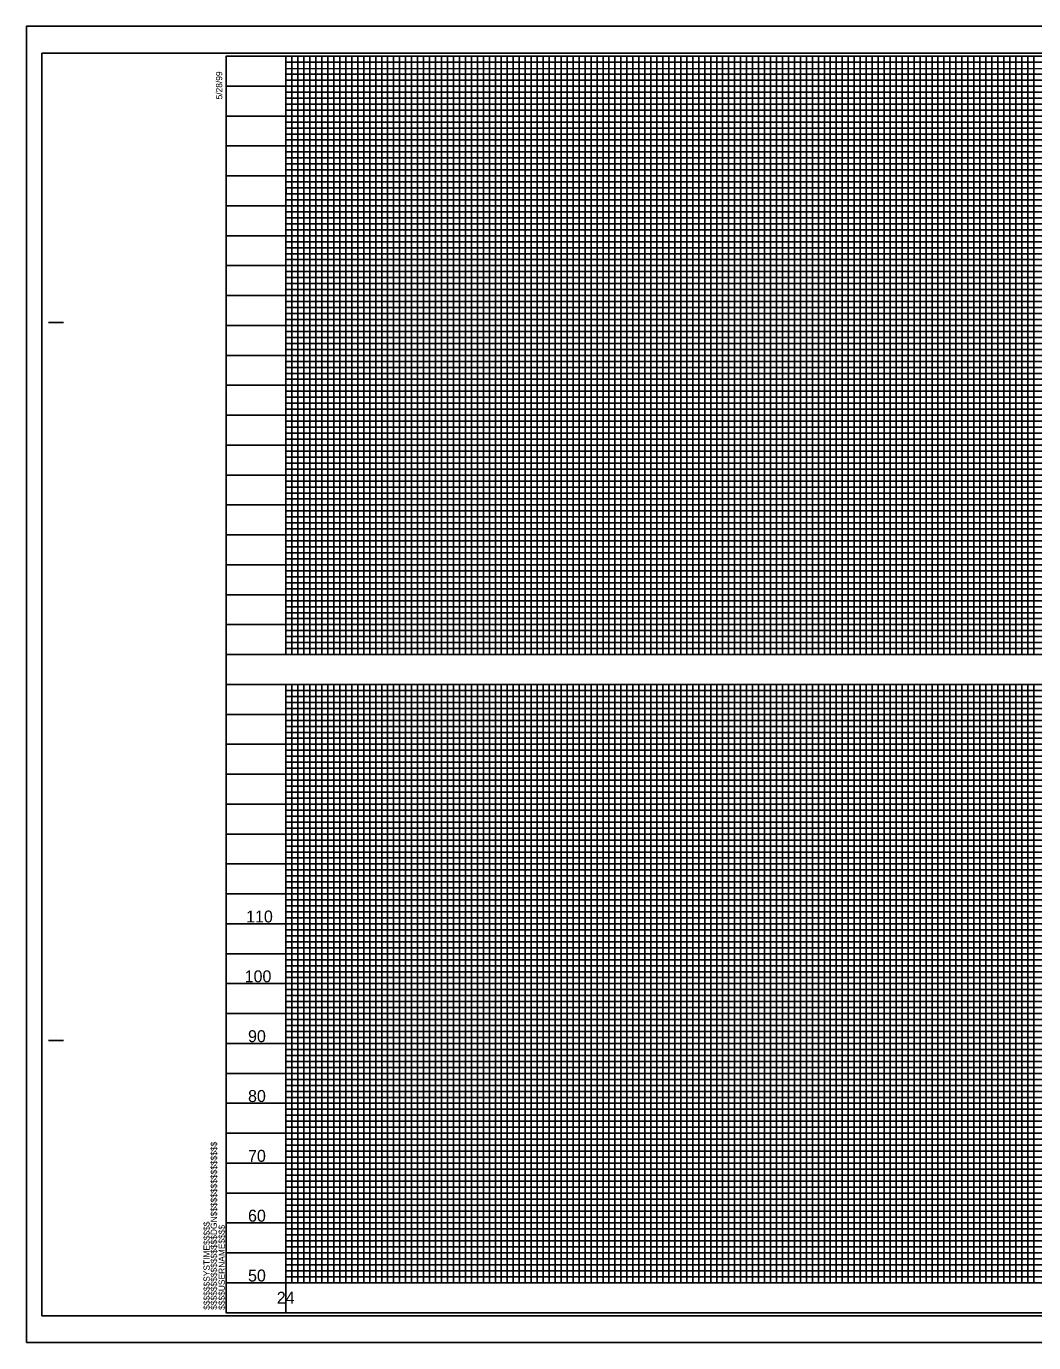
# Model space of a CAD drawing. Extents: x 2367101 to 2368930, y 803279 to 808979.
# Drawn here: x 2367101 to 2367943, y 803279 to 804379 of the extents above; entities that cross this region are included whole.
import ezdxf

# ---------------------------------------------------------------- set-up
doc = ezdxf.new("R2010")
doc.units = 0
for name, color, linetype in [('Old_Level_11', 7, 'Continuous'), ('Old_Level_12', 7, 'Continuous'), ('Old_Level_13', 7, 'Continuous'), ('Old_Level_14', 7, 'Continuous'), ('Old_Level_15', 7, 'Continuous'), ('Old_Level_17', 7, 'Continuous'), ('Old_Level_19', 7, 'Continuous'), ('Old_Level_4', 7, 'Continuous'), ('Old_Level_5', 7, 'Continuous'), ('Old_Level_6', 7, 'Continuous'), ('Old_Level_63', 7, 'Continuous'), ('Old_Level_8', 7, 'Continuous'), ('Old_Level_9', 7, 'Continuous')]:
    doc.layers.add(name, color=color, linetype=linetype)

msp = doc.modelspace()

# ---------------------------------------------------------------- linework, layer by layer
at = {"layer": 'Old_Level_11'}
for p, q in [((2367768, 803829), (2367818, 803829)), ((2367868, 803829), (2367918, 803829)), ((2367268, 803329), (2367268, 803329))]:
    msp.add_line(p, q, dxfattribs=at)
for points in [[(2367318, 804354), (2367318, 803854), (2367368, 803854), (2367368, 804354), (2367418, 804354), (2367418, 803854), (2367468, 803854), (2367468, 804354), (2367518, 804354), (2367518, 803854), (2367568, 803854), (2367568, 804354), (2367618, 804354), (2367618, 803854), (2367668, 803854), (2367668, 804354), (2367718, 804354), (2367718, 803854), (2367768, 803854), (2367768, 804354), (2367818, 804354), (2367818, 803854), (2367868, 803854), (2367868, 804354), (2367918, 804354), (2367918, 803854), (2367968, 803854)], [(2367268, 804304), (2368568, 804304)], [(2368568, 804254), (2367268, 804254), (2367268, 804204), (2368568, 804204)], [(2368768, 804154), (2367268, 804154), (2367268, 804104), (2368768, 804104)], [(2368768, 804054), (2367268, 804054), (2367268, 804004), (2368768, 804004)], [(2368768, 803954), (2367268, 803954), (2367268, 803954), (2367268, 803904), (2368768, 803904)], [(2367318, 803829), (2367318, 803329), (2367368, 803329), (2367368, 803829), (2367418, 803829), (2367418, 803329), (2367468, 803329), (2367468, 803829), (2367518, 803829), (2367518, 803329), (2367568, 803329), (2367568, 803829), (2367618, 803829), (2367618, 803329), (2367668, 803329), (2367668, 803829), (2367718, 803829), (2367718, 803329), (2367768, 803329), (2367768, 803829), (2367818, 803829), (2367818, 803329), (2367868, 803329), (2367868, 803829), (2367918, 803829), (2367918, 803329), (2367968, 803329)], [(2368768, 803779), (2367268, 803779)], [(2368768, 803729), (2367268, 803729), (2367268, 803679), (2368768, 803679)], [(2368768, 803629), (2367268, 803629), (2367268, 803579), (2368768, 803579)], [(2368768, 803529), (2367268, 803529), (2367268, 803479), (2368768, 803479)], [(2368768, 803429), (2367268, 803429), (2367268, 803429), (2367268, 803379), (2368768, 803379)], [(2368768, 803329), (2367268, 803329)]]:
    msp.add_lwpolyline(points, dxfattribs=at)
at = {"layer": 'Old_Level_12'}
msp.add_line((2367268, 804329), (2368567.9, 804329), dxfattribs=at)
for points in [[(2367343, 804354), (2367343, 803854), (2367393, 803854), (2367393, 804354), (2367443, 804354), (2367443, 803854), (2367493, 803854), (2367493, 804354), (2367543, 804354), (2367543, 803854), (2367593, 803854), (2367593, 804354), (2367643, 804354), (2367643, 803854), (2367693, 803854), (2367693, 804354), (2367743, 804354), (2367743, 803854), (2367793, 803854), (2367793, 804354), (2367843, 804354), (2367843, 803854), (2367893, 803854), (2367893, 803854), (2367893, 804354), (2367943, 804354), (2367943, 803854), (2367993, 803854)], [(2368568, 804279), (2367268, 804279), (2367268, 804229), (2368568, 804229)], [(2368768, 804179), (2367268, 804179), (2367268, 804129), (2368593, 804129)], [(2368768, 804079), (2367268, 804079), (2367268, 804029), (2368768, 804029)], [(2368768, 803979), (2367268, 803979), (2367268, 803929), (2368768, 803929)], [(2368768, 803879), (2367268, 803879)], [(2367293, 803829), (2367343, 803829), (2367343, 803329), (2367393, 803329), (2367393, 803829), (2367443, 803829), (2367443, 803329), (2367493, 803329), (2367493, 803829), (2367543, 803829), (2367543, 803329), (2367593, 803329), (2367593, 803829), (2367643, 803829), (2367643, 803329), (2367693, 803329), (2367693, 803829), (2367743, 803829), (2367743, 803329), (2367793, 803329), (2367793, 803829), (2367843, 803829), (2367843, 803329), (2367893, 803329), (2367893, 803329), (2367893, 803829), (2367943, 803829), (2367943, 803329), (2367993, 803329)], [(2367268, 803804), (2368768, 803804)], [(2368768, 803754), (2367268, 803754), (2367268, 803704), (2368768, 803704)], [(2368768, 803654), (2367268, 803654), (2367268, 803604), (2368768, 803604)], [(2368768, 803554), (2367268, 803554), (2367268, 803504), (2368768, 803504)], [(2368768, 803454), (2367268, 803454), (2367268, 803404), (2368768, 803404)], [(2368768, 803354), (2367268, 803354)]]:
    msp.add_lwpolyline(points, dxfattribs=at)
at = {"layer": 'Old_Level_13'}
for p, q in [((2367318, 803854), (2367318, 804354)), ((2367368, 803854), (2367368, 804354)), ((2367418, 803854), (2367418, 804354)), ((2367468, 803854), (2367468, 804354)), ((2367518, 803854), (2367518, 804354)), ((2367568, 803854), (2367568, 804354)), ((2367618, 803854), (2367618, 804354)), ((2367668, 803854), (2367668, 804354)), ((2367718, 803854), (2367718, 804354)), ((2367768, 803854), (2367768, 804354)), ((2367818, 803854), (2367818, 804354)), ((2367868, 803854), (2367868, 804354)), ((2367918, 803854), (2367918, 804354)), ((2368567.9, 804304), (2367268, 804304)), ((2368567.9, 804254), (2367268, 804254)), ((2368568, 804204), (2367268, 804204)), ((2368768, 804154), (2367268, 804154)), ((2368768, 804104), (2367268, 804104)), ((2368768, 804054), (2367268, 804054)), ((2368768, 804004), (2367268, 804004)), ((2368768, 803954), (2367268, 803954)), ((2368768, 803904), (2367268, 803904)), ((2367268, 803829), (2368767.9, 803829)), ((2367318, 803829), (2367318, 803329)), ((2367368, 803829), (2367368, 803329)), ((2367418, 803829), (2367418, 803329)), ((2367468, 803829), (2367468, 803329)), ((2367518, 803829), (2367518, 803329)), ((2367568, 803829), (2367568, 803329)), ((2367618, 803829), (2367618, 803329)), ((2367668, 803829), (2367668, 803329)), ((2367718, 803829), (2367718, 803329)), ((2367768, 803829), (2367768, 803329)), ((2367818, 803829), (2367818, 803329)), ((2367868, 803829), (2367868, 803329)), ((2367918, 803829), (2367918, 803329)), ((2367268, 803779), (2368767.9, 803779)), ((2367268, 803729), (2368767.9, 803729)), ((2367268, 803679), (2368767.9, 803679)), ((2367268, 803629), (2368767.9, 803629)), ((2367268, 803579), (2368767.9, 803579)), ((2367268, 803529), (2368767.9, 803529)), ((2367268, 803479), (2368767.9, 803479)), ((2367268, 803429), (2368767.9, 803429)), ((2367268, 803379), (2368767.9, 803379))]:
    msp.add_line(p, q, dxfattribs=at)
at = {"layer": 'Old_Level_14'}
msp.add_line((2367318, 803329), (2367318, 803304), dxfattribs=at)
at = {"layer": 'Old_Level_15'}
for p, q in [((2368785, 804379), (2367101, 804379)), ((2367101, 804379), (2367101, 803279)), ((2367101, 803279), (2368785, 803279))]:
    msp.add_line(p, q, dxfattribs=at)
at = {"layer": 'Old_Level_4'}
msp.add_lwpolyline([(2367114, 803301.4), (2368780.5, 803301.4), (2368780.5, 804356.5), (2367114, 804356.5)], close=True, dxfattribs=at)
at = {"layer": 'Old_Level_5'}
msp.add_lwpolyline([(2367318, 803829), (2368718, 803829), (2368718, 803329), (2367318, 803329)], close=True, dxfattribs=at)
at = {"layer": 'Old_Level_6'}
msp.add_lwpolyline([(2367101, 803279), (2368785, 803279), (2368785, 804379), (2367101, 804379)], close=True, dxfattribs=at)
at = {"layer": 'Old_Level_63'}
msp.add_lwpolyline([(2367318, 804192.9), (2367318, 803854), (2368718, 803854), (2368718, 804192.9)], dxfattribs=at)
at = {"layer": 'Old_Level_8'}
for p, q in [((2367318, 804349), (2368568, 804349)), ((2367318, 804344), (2367318, 804344)), ((2368568, 804344), (2367318, 804343.6)), ((2367318, 804339), (2368568, 804339)), ((2368567.9, 804219), (2367318, 804219)), ((2368568, 804214), (2367318, 804214)), ((2368568, 804209), (2367318, 804209)), ((2367318, 804199), (2368568, 804199)), ((2368568, 804194), (2367318, 804194)), ((2367318, 804189), (2368718, 804189)), ((2368718, 804169), (2367318, 804169)), ((2367318, 804164), (2368718, 804164)), ((2368718, 804144), (2367318, 804144)), ((2367318, 804139), (2368718, 804139)), ((2368718, 804119), (2367318, 804119)), ((2367318, 804114), (2368718, 804114)), ((2368718, 804109), (2367318, 804109)), ((2367318, 804099), (2368718, 804099)), ((2368718, 804094), (2367318, 804094)), ((2367318, 804089), (2368718, 804089)), ((2368718, 804084), (2367318, 804084)), ((2367318, 804074), (2368718, 804074)), ((2368718, 804069), (2367318, 804069)), ((2367318, 804064), (2368718, 804064)), ((2368718, 804059), (2367318, 804059)), ((2367318, 804049), (2368718, 804049)), ((2368718, 804044), (2367318, 804044)), ((2367318, 804039), (2368718, 804039)), ((2368718, 804034), (2367318, 804034)), ((2367318, 804024), (2368718, 804024)), ((2368718, 804019), (2367318, 804019)), ((2367318, 804014), (2368718, 804014)), ((2368718, 804009), (2367318, 804009)), ((2367318, 803999), (2368718, 803999)), ((2368718, 803994), (2367318, 803994)), ((2367318, 803989), (2368718, 803989)), ((2368718, 803984), (2367318, 803984)), ((2367318, 803974), (2368718, 803974)), ((2368718, 803969), (2367318, 803969)), ((2368718, 803964), (2367318, 803964)), ((2368718, 803959), (2367318, 803959)), ((2367318, 803949), (2368718, 803949)), ((2368718, 803944), (2367318, 803944)), ((2367318, 803939), (2368718, 803939)), ((2368718, 803934), (2367318, 803934)), ((2367318, 803924), (2368718, 803924)), ((2368718, 803919), (2367318, 803919)), ((2367318, 803914), (2368718, 803914)), ((2368718, 803909), (2367318, 803909)), ((2367318, 803899), (2368718, 803899)), ((2368718, 803894), (2367318, 803894)), ((2367318, 803889), (2368718, 803889)), ((2368718, 803884), (2367318, 803884)), ((2367318, 803874), (2368718, 803874)), ((2368718, 803869), (2367318, 803869)), ((2367318, 803864), (2368718, 803864)), ((2367318, 803824), (2368718, 803824)), ((2368718, 803819), (2367318, 803819)), ((2367318, 803814), (2368718, 803814)), ((2368718, 803809), (2367318, 803809)), ((2367318, 803799), (2368718, 803799)), ((2368718, 803794), (2367318, 803794)), ((2367318, 803789), (2368718, 803789)), ((2368718, 803784), (2367318, 803784)), ((2367318, 803774), (2368718, 803774)), ((2368718, 803769), (2367318, 803769)), ((2367318, 803764), (2368718, 803764)), ((2368718, 803759), (2367318, 803759)), ((2367318, 803749), (2368718, 803749)), ((2368718, 803744), (2367318, 803744)), ((2367318, 803739), (2368718, 803739)), ((2368718, 803734), (2367318, 803734)), ((2367318, 803724), (2368718, 803724)), ((2368718, 803719), (2367318, 803719)), ((2367318, 803714), (2368718, 803714)), ((2368718, 803709), (2367318, 803709)), ((2367318, 803699), (2368718, 803699)), ((2368718, 803694), (2367318, 803694)), ((2367318, 803689), (2368718, 803689)), ((2368718, 803684), (2367318, 803684)), ((2367318, 803674), (2368718, 803674)), ((2368718, 803669), (2367318, 803669)), ((2367318, 803664), (2368718, 803664)), ((2368718, 803659), (2367318, 803659)), ((2367318, 803649), (2368718, 803649)), ((2368718, 803644), (2367318, 803644)), ((2367318, 803639), (2368718, 803639)), ((2368718, 803634), (2367318, 803634.1)), ((2367318, 803624), (2368718, 803624)), ((2368718, 803619), (2367318, 803619)), ((2367318, 803614), (2368718, 803614)), ((2368718, 803609), (2367318, 803609)), ((2367318, 803599), (2368718, 803599)), ((2368718, 803594), (2367318, 803594)), ((2367318, 803589), (2368718, 803589)), ((2368718, 803584), (2367318, 803584)), ((2367318, 803574), (2368718, 803574)), ((2368718, 803569), (2367318, 803569)), ((2367318, 803564), (2368718, 803564)), ((2368718, 803559), (2367318, 803559)), ((2367318, 803549), (2368718, 803549)), ((2368718, 803544), (2367318, 803544)), ((2367318, 803539), (2368718, 803539)), ((2368718, 803534), (2367318, 803534)), ((2367318, 803524), (2368718, 803524)), ((2368718, 803519), (2367318, 803519)), ((2367318, 803514), (2368718, 803514)), ((2368718, 803509), (2367318, 803509)), ((2367318, 803499), (2368718, 803499)), ((2368718, 803494), (2367318, 803494)), ((2367318, 803489), (2368718, 803489)), ((2368718, 803484), (2367318, 803484)), ((2367318, 803474), (2368718, 803474)), ((2368718, 803469), (2367318, 803469)), ((2367318, 803464), (2368718, 803464)), ((2368718, 803459), (2367318, 803459)), ((2367318, 803449), (2368718, 803449)), ((2368718, 803444), (2367318, 803444)), ((2367318, 803439), (2368718, 803439)), ((2368718, 803434), (2367318, 803434)), ((2367318, 803424), (2368718, 803424)), ((2368718, 803419), (2367318, 803419)), ((2367318, 803414), (2368718, 803414)), ((2368718, 803409), (2367318, 803409)), ((2367318, 803399), (2368718, 803399)), ((2368718, 803394), (2367318, 803394)), ((2367318, 803389), (2368718, 803389)), ((2368718, 803384), (2367318, 803384)), ((2367318, 803374), (2368718, 803374)), ((2368718, 803369), (2367318, 803369)), ((2367318, 803364), (2368718, 803364)), ((2368718, 803359), (2367318, 803359)), ((2367318, 803349), (2368718, 803349)), ((2368718, 803344), (2367318, 803344)), ((2367318, 803339), (2368718, 803339)), ((2367318, 803334), (2368718, 803334))]:
    msp.add_line(p, q, dxfattribs=at)
for points in [[(2367323, 804354), (2367323, 803854), (2367328, 803854), (2367328, 804354), (2367333, 804354), (2367333, 803854), (2367338, 803854), (2367338, 804354), (2367348, 804354), (2367348, 803854), (2367353, 803854), (2367353, 804354), (2367358, 804354), (2367358, 803854), (2367363, 803854), (2367373, 803854), (2367378, 803854), (2367378, 804354), (2367383, 804354), (2367383, 803854), (2367388, 803854), (2367388, 804354), (2367398, 804354), (2367398, 803854), (2367403, 803854), (2367403, 804354), (2367408, 804354), (2367408, 803854), (2367413, 803854), (2367413, 804354), (2367423, 804354), (2367423, 803854), (2367428, 803854), (2367428, 804354), (2367433, 804354), (2367433, 803854), (2367438, 803854), (2367438, 804354), (2367448, 804354), (2367448, 803854), (2367453, 803854), (2367453, 804354), (2367458, 804354), (2367458, 803854), (2367463, 803854), (2367463, 804354), (2367473, 804354), (2367473, 803854), (2367478, 803854), (2367478, 804354), (2367483, 804354), (2367483, 803854), (2367488, 803854), (2367488, 804354), (2367498, 804354), (2367498, 803854), (2367503, 803854), (2367503, 804354), (2367508, 804354), (2367508, 803854), (2367513, 803854), (2367513, 804354), (2367523, 804354), (2367523, 803854), (2367528, 803854), (2367528, 804354), (2367533, 804354), (2367533, 803854)], [(2367363, 803854), (2367363, 804354), (2367373, 804354), (2367373, 803854)], [(2367533, 803854), (2367538, 803854), (2367538, 804354), (2367548, 804354), (2367548, 803854), (2367553, 803854), (2367553, 804354), (2367558, 804354), (2367558, 803854), (2367563, 803854), (2367563, 804354), (2367573, 804354), (2367573, 803854), (2367578, 803854), (2367578, 804354), (2367583, 804354), (2367583, 803854), (2367588, 803854), (2367588, 804354), (2367598, 804354), (2367598, 803854), (2367603, 803854), (2367603, 804354), (2367608, 804354), (2367608, 803854), (2367613, 803854), (2367613, 804354), (2367623, 804354), (2367623, 803854), (2367628, 803854), (2367628, 804354), (2367633, 804354), (2367633, 803854), (2367638, 803854), (2367638, 804354), (2367648, 804354), (2367648, 803854), (2367653, 803854), (2367653, 804354), (2367658, 804354), (2367658, 803854), (2367663, 803854), (2367663, 804354), (2367673, 804354), (2367673, 803854), (2367678, 803854), (2367678, 804354), (2367683, 804354), (2367683, 803854), (2367688, 803854), (2367688, 804354), (2367698, 804354), (2367698, 803854), (2367703, 803854), (2367703, 804354), (2367708, 804354), (2367708, 803854), (2367713, 803854), (2367713, 804354), (2367723, 804354), (2367723, 803854), (2367728, 803854), (2367728, 804354), (2367733, 804354), (2367733, 803854), (2367738, 803854), (2367738, 804354), (2367748, 804354), (2367748, 803854), (2367753, 803854), (2367753, 804354), (2367758, 804354), (2367758, 803854), (2367763, 803854), (2367763, 804354), (2367773, 804354), (2367773, 803854), (2367778, 803854), (2367778, 804354), (2367783, 804354), (2367783, 803854), (2367788, 803854), (2367788, 804354), (2367798, 804354), (2367798, 803854), (2367803, 803854), (2367803, 804354), (2367808, 804354), (2367808, 803854), (2367813, 803854), (2367813, 804354), (2367823, 804354), (2367823, 803854), (2367828, 803854), (2367828, 804354), (2367833, 804354), (2367833, 803854), (2367838, 803854), (2367838, 804354), (2367848, 804354)], [(2367848, 804354), (2367848, 803854), (2367853, 803854), (2367853, 804354), (2367858, 804354), (2367858, 803854), (2367863, 803854), (2367863, 804354), (2367873, 804354), (2367873, 803854), (2367878, 803854), (2367878, 804354), (2367883, 804354), (2367883, 803854), (2367888, 803854), (2367888, 804354), (2367898, 804354), (2367898, 803854), (2367903, 803854), (2367903, 804354), (2367908, 804354), (2367908, 803854), (2367913, 803854), (2367913, 804354), (2367923, 804354), (2367923, 803854), (2367928, 803854), (2367928, 804354), (2367933, 804354), (2367933, 803854), (2367938, 803854), (2367938, 804354), (2367948, 804354)], [(2368568, 804334), (2367318, 804334), (2367318, 804324), (2368568, 804324)], [(2368567.9, 804319), (2367318, 804319), (2367318, 804314), (2368568, 804314)], [(2368568, 804309), (2367318, 804309), (2367318, 804299), (2368568, 804299)], [(2368568, 804294), (2367318, 804294), (2367318, 804289), (2368568, 804289)], [(2368568, 804284), (2367318, 804284), (2367318, 804274), (2368568, 804274)], [(2368568, 804269), (2367318, 804269), (2367318, 804264), (2368568, 804264)], [(2368568, 804259), (2367318, 804259), (2367318, 804249), (2368568, 804249)], [(2368568, 804243.9), (2367318.1, 804243.9), (2367318.1, 804239), (2368568, 804239)], [(2368568, 804234), (2367318, 804234), (2367318, 804224), (2368568, 804224)], [(2368718, 804184), (2367318, 804184), (2367318, 804174), (2368718, 804174)], [(2368718, 804159), (2367318, 804159), (2367318, 804149), (2368718, 804149)], [(2368718, 804134), (2367318, 804134), (2367318, 804124), (2368718, 804124)], [(2368718, 803859), (2367318, 803859)], [(2367318, 803829), (2367323, 803829), (2367323, 803329), (2367328, 803329), (2367328, 803829), (2367333, 803829), (2367333, 803329), (2367338, 803329), (2367338, 803829), (2367348, 803829), (2367348, 803329), (2367353, 803329), (2367353, 803829), (2367358, 803829), (2367358, 803329), (2367363, 803329), (2367373, 803329), (2367378, 803329), (2367378, 803829), (2367383, 803829), (2367383, 803329), (2367388, 803329), (2367388, 803829), (2367398, 803829), (2367398, 803329), (2367403, 803329), (2367403, 803829), (2367408, 803829), (2367408, 803329), (2367413, 803329), (2367413, 803829), (2367423, 803829), (2367423, 803329), (2367428, 803329), (2367428, 803829), (2367433, 803829), (2367433, 803329), (2367438, 803329), (2367438, 803829), (2367448, 803829), (2367448, 803329), (2367453, 803329), (2367453, 803829), (2367458, 803829), (2367458, 803329), (2367463, 803329), (2367463, 803829), (2367473, 803829), (2367473, 803329), (2367478, 803329), (2367478, 803829), (2367483, 803829), (2367483, 803329), (2367488, 803329), (2367488, 803829), (2367498, 803829), (2367498, 803329), (2367503, 803329), (2367503, 803829), (2367508, 803829), (2367508, 803329), (2367513, 803329), (2367513, 803829), (2367523, 803829), (2367523, 803329), (2367528, 803329), (2367528, 803829), (2367533, 803829), (2367533, 803329)], [(2367363, 803329), (2367363, 803829), (2367373, 803829), (2367373, 803329)], [(2367533, 803329), (2367538, 803329), (2367538, 803829), (2367548, 803829), (2367548, 803329), (2367553, 803329), (2367553, 803829), (2367558, 803829), (2367558, 803329), (2367563, 803329), (2367563, 803829), (2367573, 803829), (2367573, 803329), (2367578, 803329), (2367578, 803829), (2367583, 803829), (2367583, 803329), (2367588, 803329), (2367588, 803829), (2367598, 803829), (2367598, 803329), (2367603, 803329), (2367603, 803829), (2367608, 803829), (2367608, 803329), (2367613, 803329), (2367613, 803829), (2367623, 803829), (2367623, 803329), (2367628, 803329), (2367628, 803829), (2367633, 803829), (2367633, 803329), (2367638, 803329), (2367638, 803829), (2367648, 803829), (2367648, 803329), (2367653, 803329), (2367653, 803829), (2367658, 803829), (2367658, 803329), (2367663, 803329), (2367663, 803829), (2367673, 803829), (2367673, 803329), (2367678, 803329), (2367678, 803829), (2367683, 803829), (2367683, 803329), (2367688, 803329), (2367688, 803829), (2367698, 803829), (2367698, 803329), (2367703, 803329), (2367703, 803829), (2367708, 803829), (2367708, 803329), (2367713, 803329), (2367713, 803829), (2367723, 803829), (2367723, 803329), (2367728, 803329), (2367728, 803829), (2367733, 803829), (2367733, 803329), (2367738, 803329), (2367738, 803829), (2367748, 803829), (2367748, 803329), (2367753, 803329), (2367753, 803829), (2367758, 803829), (2367758, 803329), (2367763, 803329), (2367763, 803829), (2367773, 803829), (2367773, 803329), (2367778, 803329), (2367778, 803829), (2367783, 803829), (2367783, 803329), (2367788, 803329), (2367788, 803829), (2367798, 803829), (2367798, 803329), (2367803, 803329), (2367803, 803829), (2367808, 803829), (2367808, 803329), (2367813, 803329), (2367813, 803829), (2367823, 803829), (2367823, 803329), (2367828, 803329), (2367828, 803829), (2367833, 803829), (2367833, 803329), (2367838, 803329), (2367838, 803829), (2367848, 803829)], [(2367848, 803829), (2367848, 803329), (2367853, 803329), (2367853, 803829), (2367858, 803829), (2367858, 803329), (2367863, 803329), (2367863, 803829), (2367873, 803829), (2367873, 803329), (2367878, 803329), (2367878, 803829), (2367883, 803829), (2367883, 803329), (2367888, 803329), (2367888, 803829), (2367898, 803829), (2367898, 803329), (2367903, 803329), (2367903, 803829), (2367908, 803829), (2367908, 803329), (2367913, 803329), (2367913, 803829), (2367923, 803829), (2367923, 803329), (2367928, 803329), (2367928, 803829), (2367933, 803829), (2367933, 803329), (2367938, 803329), (2367938, 803829), (2367948, 803829)]]:
    msp.add_lwpolyline(points, dxfattribs=at)
at = {"layer": 'Old_Level_9'}
for p, q in [((2367119.5, 804131.5), (2367132, 804131.5)), ((2367268, 803854), (2368768, 803854)), ((2367268, 803829), (2368768, 803829)), ((2367119.5, 803531.5), (2367132, 803531.5)), ((2368768, 803329), (2367268, 803329)), ((2367268, 803304), (2368768, 803304)), ((2367268, 803304), (2367268, 803304)), ((2367268, 803304), (2367268, 803304)), ((2367268, 803304), (2367268, 803304)), ((2367268, 803304), (2367268, 803304)), ((2367268, 803304), (2367268, 803304)), ((2367268, 803304), (2367268, 803304)), ((2367268, 803304), (2367268, 803304))]:
    msp.add_line(p, q, dxfattribs=at)
msp.add_lwpolyline([(2368768, 804354), (2367268, 804354), (2367268, 803304), (2368768, 803304)], close=True, dxfattribs=at)
msp.add_lwpolyline([(2367305.5, 803304), (2367305.5, 803304)], dxfattribs=at)

# ---------------------------------------------------------------- texts
at = {"layer": 'Old_Level_17'}
for s, p in [('110', (2367284.7, 803630.1)), ('100', (2367283.5, 803580.1)), ('90', (2367286.3, 803530.1)), ('80', (2367286.3, 803480.1)), ('70', (2367286.3, 803430.1)), ('60', (2367286.3, 803380.1)), ('50', (2367286.3, 803330.1))]:
    msp.add_text(s, height=10, dxfattribs=at).set_placement(p)
at = {"layer": 'Old_Level_19'}
msp.add_text('24', height=10, dxfattribs=at).set_placement((2367310.3, 803311.5))
at = {"layer": 'Old_Level_9'}
for s, p in [('5/28/99', (2367264.7, 804317.9)), ('$$$$$$$$$$$$$$$$DGN$$$$$$$$$$$$$$$$', (2367260.3, 803306.4)), ('$$$$$$SYSTIME$$$$$', (2367254.3, 803306.4)), ('$$$$USERNAME$$$$', (2367266.9, 803306.4))]:
    msp.add_text(s, height=5.25, rotation=90, dxfattribs=at).set_placement(p)

doc.saveas('drawing.dxf')
